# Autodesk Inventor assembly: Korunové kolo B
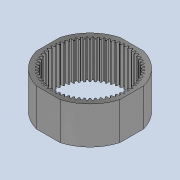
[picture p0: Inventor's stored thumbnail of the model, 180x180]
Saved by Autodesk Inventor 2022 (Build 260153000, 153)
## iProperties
Created: 2025-05
Part Number: Korunové kolo B
Document SubType Name: Assembly
Designer: jbart
Mass: 5966.28 g
Surface Area: 6901.86 cm^2
Volume: 5966.28 cm^3
Density: 1 g/cm^3
Author: jbart
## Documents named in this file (2)
- C:\Users\jbart\OneDrive\Dokumenty\Inventor\Převodovka navijáku\Korunové kolo 2.iam
- C:\Users\jbart\OneDrive\Dokumenty\Inventor\Převodovka navijáku\Korunové kolo 2\Design Accelerator\Čelní ozubená kola1.iam
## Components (1 placed, 1 different names)
1. Čelní ozubená kola:1 [sub-assembly]
